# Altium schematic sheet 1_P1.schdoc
size 307 x 218 mm; Symbol: Drawing-Symbol_A4; Device: Drawing-Symbol_A4; Company: 嘉立创EDA; Version: V1.0; Page Size: A4; @Project Name: 741; @Page Count: 1; @Update Date: 2025-12-01; @Create Date: 2025-11-30; @Schematic Name: 741_Schematic; @Page No: 1; @Page Name: P1; @Board Name: Board1; @Create Time: 14:58:41; @Update Time: 02:35:05; Title Block Position: 3; Size: A4; Width: 1170; Height: 825; Region Start: 1; X Region Count: 6; Y Region Count: 4; Blade Width: 10
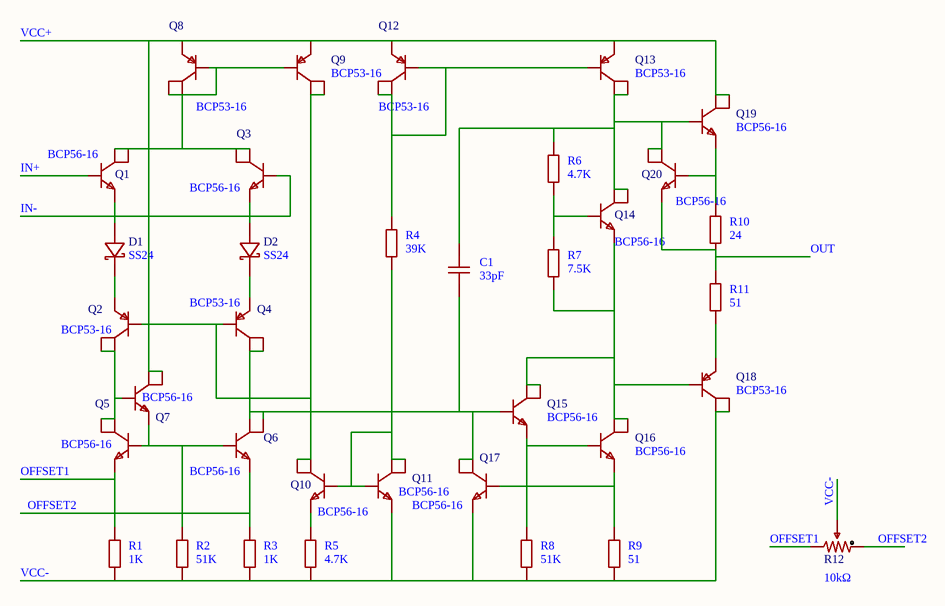
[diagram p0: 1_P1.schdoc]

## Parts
C1  33pF  [C0805]
D1  SS24  [SMA_L4.3-W2.6-LS5.0-FD]
D2  SS24  [SMA_L4.3-W2.6-LS5.0-FD]
Q1  BCP56-16  [SOT-223-4_L6.5-W3.5-P2.30-LS7.0-BR]
Q2  BCP53-16  [SOT-223-3_L6.7-W3.7-P2.30-LS7.0-BR]
Q3  BCP56-16  [SOT-223-4_L6.5-W3.5-P2.30-LS7.0-BR]
Q4  BCP53-16  [SOT-223-3_L6.7-W3.7-P2.30-LS7.0-BR]
Q5  BCP56-16  [SOT-223-4_L6.5-W3.5-P2.30-LS7.0-BR]
Q6  BCP56-16  [SOT-223-4_L6.5-W3.5-P2.30-LS7.0-BR]
Q7  BCP56-16  [SOT-223-4_L6.5-W3.5-P2.30-LS7.0-BR]
Q8  BCP53-16  [SOT-223-3_L6.7-W3.7-P2.30-LS7.0-BR]
Q9  BCP53-16  [SOT-223-3_L6.7-W3.7-P2.30-LS7.0-BR]
Q10  BCP56-16  [SOT-223-4_L6.5-W3.5-P2.30-LS7.0-BR]
Q11  BCP56-16  [SOT-223-4_L6.5-W3.5-P2.30-LS7.0-BR]
Q12  BCP53-16  [SOT-223-3_L6.7-W3.7-P2.30-LS7.0-BR]
Q13  BCP53-16  [SOT-223-3_L6.7-W3.7-P2.30-LS7.0-BR]
Q14  BCP56-16  [SOT-223-4_L6.5-W3.5-P2.30-LS7.0-BR]
Q15  BCP56-16  [SOT-223-4_L6.5-W3.5-P2.30-LS7.0-BR]
Q16  BCP56-16  [SOT-223-4_L6.5-W3.5-P2.30-LS7.0-BR]
Q17  BCP56-16  [SOT-223-4_L6.5-W3.5-P2.30-LS7.0-BR]
Q18  BCP53-16  [SOT-223-3_L6.7-W3.7-P2.30-LS7.0-BR]
Q19  BCP56-16  [SOT-223-4_L6.5-W3.5-P2.30-LS7.0-BR]
Q20  BCP56-16  [SOT-223-4_L6.5-W3.5-P2.30-LS7.0-BR]
R1  1K  [R0805]
R2  51K  [R0805]
R3  1K  [R0805]
R4  39K  [R0805]
R5  4.7K  [R0805]
R6  4.7K  [R0805]
R7  7.5K  [R0805]
R8  51K  [R0805]
R9  51  [R0805]
R10  24  [R0805]
R11  51  [R0805]
R12  10kΩ  [电位器]

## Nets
IN+: Q1.1(B)
IN-: Q3.1(B)
OFFSET1: Q5.3(E) R1.2 R12.3
OFFSET2: Q6.3(E) R3.2 R12.1
OUT: Q20.3(E) R10.1 R11.2
VCC+: Q7.2(C) Q7.4(C) Q8.3(E) Q9.3(E) Q12.3(E) Q13.3(E) Q19.2(C) Q19.4(C)
VCC-: Q11.3(E) Q17.3(E) Q18.2(C) Q18.4(C) R1.1 R2.1 R3.1 R5.1 R8.1 R9.1 R12.2
NetC1_1: C1.1 Q4.2(C) Q4.4(C) Q6.2(C) Q6.4(C) Q15.1(B) Q17.2(C) Q17.4(C)
NetC1_2: C1.2 Q13.2(C) Q13.4(C) Q14.2(C) Q14.4(C) Q19.1(B) Q20.2(C) Q20.4(C) R6.2
NetD1_1: D1.1(A) Q1.3(E)
NetD1_2: D1.2(K) Q2.3(E)
NetD2_1: D2.1(A) Q3.3(E)
NetD2_2: D2.2(K) Q4.3(E)
NetQ1_2: Q1.2(C) Q1.4(C) Q3.2(C) Q3.4(C) Q8.1(B) Q8.2(C) Q8.4(C) Q9.1(B)
NetQ2_1: Q2.1(B) Q4.1(B) Q9.2(C) Q9.4(C) Q10.2(C) Q10.4(C)
NetQ2_2: Q2.2(C) Q2.4(C) Q5.2(C) Q5.4(C) Q7.1(B)
NetQ5_1: Q5.1(B) Q6.1(B) Q7.3(E) R2.2
NetQ10_1: Q10.1(B) Q11.1(B) Q11.2(C) Q11.4(C) R4.1
NetQ10_3: Q10.3(E) R5.2
NetQ12_1: Q12.1(B) Q12.2(C) Q12.4(C) Q13.1(B) R4.2
NetQ14_1: Q14.1(B) R6.1 R7.2
NetQ14_3: Q14.3(E) Q15.2(C) Q15.4(C) Q16.2(C) Q16.4(C) Q18.1(B) R7.1
NetQ15_3: Q15.3(E) Q16.1(B) R8.2
NetQ16_3: Q16.3(E) Q17.1(B) R9.2
NetQ18_3: Q18.3(E) R11.1
NetQ19_3: Q19.3(E) Q20.1(B) R10.2

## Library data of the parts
C1 = CAP_0805: Symbol: Capacitance; Convert to PCB: yes
D1 D2 = SS24_C7420362: Manufacturer: R+O(宏嘉诚); Add into BOM: yes; Diode Configuration: 独立式; Voltage - Forward(Vf@If): 550mV@2A; Voltage - DC Reverse(Vr): 40V; Current - Rectified: 2A; Reverse Leakage Current (Ir): 200uA@40V; Operating Junction Temperature Range: -55℃~+150℃; Non-Repetitive Peak Forward Surge Current: 50A
Q1 Q3 Q5-Q7 Q10 Q11 Q14-Q17 Q19 Q20 = BCP56-16_C41375109: Manufacturer: R+O(宏嘉诚); Add into BOM: yes; type: NPN; Current - Collector(Ic): 1A; Collector - Emitter Voltage VCEO: 80V; Pd - Power Dissipation: 1.33W; DC Current Gain: 25@5mA,2V; Transition frequency(fT): 130MHz; Current - Collector Cutoff: 100nA; Vce Saturation(VCE(sat)): 500mV@500mA,50mA; Emitter-Base Voltage(Vebo): 5V
Q2 Q4 Q8 Q9 Q12 Q13 Q18 = BCP53-16_C41375110: Manufacturer: R+O(宏嘉诚); Add into BOM: yes; type: PNP; Current - Collector(Ic): 1A; Collector - Emitter Voltage VCEO: 100V; Pd - Power Dissipation: 1.5W; DC Current Gain: 250@150mA,3V; Transition frequency(fT): 100MHz; Current - Collector Cutoff: 100nA; Vce Saturation(VCE(sat)): 500mV@500mA,50mA; Emitter-Base Voltage(Vebo): 5V
R1-R11 = Res_0805: Symbol: 电阻; Convert to PCB: yes
R12 = 3296W-1-103_C48997937: Manufacturer: JIERR(捷而瑞); Add into BOM: yes; Tolerance: ±10%; Power(Watts): 500mW; Temperature Coefficient: ±250ppm/℃; Number of Turns: 28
